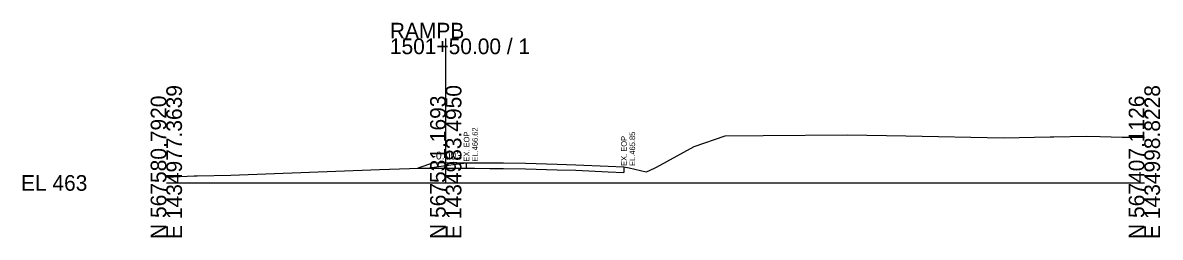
# Model space of a CAD drawing. Extents: x 1431908 to 1449087, y 567604 to 577825.
# Drawn here: x 1439484.4 to 1439688, y 573048.6 to 573086.9 of the extents above; entities that cross this region are included whole.
import ezdxf

# ---------------------------------------------------------------- set-up
doc = ezdxf.new("R2010")
doc.units = 0
for name, color, linetype in [('DESIGN - SHEET - Light Grid', 7, 'Continuous'), ('DESIGN - TYPICAL - Finished Grade and Subgrade', 7, 'Continuous'), ('SURVEY - GROUND - Existing Pavement Layer', 7, 'Continuous'), ('SURVEY - GROUND - Existing Pavement Text', 7, 'Continuous'), ('SURVEY - GROUND - Top of Ground', 7, 'Continuous')]:
    doc.layers.add(name, color=color, linetype=linetype)

msp = doc.modelspace()

# ---------------------------------------------------------------- linework, layer by layer
at = {"layer": 'DESIGN - SHEET - Light Grid'}
for p, q in [((1439560.12, 573058.33), (1439560.12, 573084.13)), ((1439510.12, 573058.33), (1439560.12, 573058.33)), ((1439560.12, 573058.33), (1439685.12, 573058.33))]:
    msp.add_line(p, q, dxfattribs=at)
at = {"layer": 'DESIGN - TYPICAL - Finished Grade and Subgrade'}
for q in [(1439555.12, 573060.97), (1439565.26, 573061.94)]:
    msp.add_line((1439558.12, 573061.97), q, dxfattribs=at)
at = {"layer": 'SURVEY - GROUND - Existing Pavement Layer'}
for p, q in [((1439555.15, 573060.98), (1439565.26, 573060.94)), ((1439563.85, 573060.95), (1439563.85, 573061.95)), ((1439565.26, 573060.94), (1439568, 573060.93)), ((1439568, 573060.93), (1439570.46, 573060.9)), ((1439570.46, 573060.9), (1439574.38, 573060.85)), ((1439574.38, 573060.85), (1439580.05, 573060.69)), ((1439580.05, 573060.69), (1439583.38, 573060.59)), ((1439583.38, 573060.59), (1439589.15, 573060.32)), ((1439589.15, 573060.32), (1439592, 573060.18)), ((1439592, 573061.18), (1439592, 573060.18))]:
    msp.add_line(p, q, dxfattribs=at)
at = {"layer": 'SURVEY - GROUND - Top of Ground'}
msp.add_lwpolyline([(1439510.12, 573059.35), (1439515.11, 573059.58), (1439515.63, 573059.6), (1439521.68, 573059.71), (1439548.27, 573060.71), (1439557.18, 573061.03), (1439560.12, 573061.44), (1439563.85, 573061.95), (1439565.26, 573061.94), (1439568, 573061.93), (1439570.46, 573061.9), (1439574.38, 573061.85), (1439580.05, 573061.69), (1439583.38, 573061.59), (1439589.15, 573061.32), (1439592, 573061.18), (1439592.95, 573061), (1439593.94, 573060.82), (1439595.98, 573060.33), (1439596.45, 573060.52), (1439597.82, 573061.15), (1439604.54, 573064.86), (1439610.11, 573066.74), (1439616.89, 573066.79), (1439632.02, 573066.93), (1439642.43, 573066.74), (1439659.91, 573066.36), (1439668.26, 573066.55), (1439668.9, 573066.57), (1439674.68, 573066.68), (1439677.21, 573066.6), (1439681.16, 573066.49), (1439684.47, 573066.49), (1439685.12, 573066.48)], dxfattribs=at)

# ---------------------------------------------------------------- texts
at = {"layer": 'DESIGN - SHEET - Light Grid'}
for s, p in [('RAMPB', (1439550.12, 573084.13)), ('1501+50.00 / 1', (1439550.12, 573081.33)), ('EL 463', (1439484.12, 573056.93))]:
    msp.add_text(s, height=2.8, dxfattribs=at).set_placement(p)
for s, p in [('E 1434977.3639', (1439512.92, 573048.33)), ('E 1434983.4950', (1439562.92, 573048.33)), ('E 1434998.8228', (1439687.92, 573048.33)), ('N 567580.7920', (1439510.12, 573048.33)), ('N 567531.1693', (1439560.12, 573048.33)), ('N 567407.1126', (1439685.12, 573048.33))]:
    msp.add_text(s, height=2.8, rotation=90, dxfattribs=at).set_placement(p)
at = {"layer": 'DESIGN - TYPICAL - Finished Grade and Subgrade'}
msp.add_text('-0.003', height=1.4, rotation=359.8012, dxfattribs=at).set_placement((1439557.72, 573062.53))
at = {"layer": 'SURVEY - GROUND - Existing Pavement Text'}
for s, p in [('EX. EOP', (1439564.35, 573062.15)), ('EL.466.62', (1439565.85, 573062.15)), ('EX. EOP', (1439592.5, 573061.38)), ('EL.465.85', (1439594, 573061.38))]:
    msp.add_text(s, height=1, rotation=90, dxfattribs=at).set_placement(p)

doc.saveas('drawing.dxf')
